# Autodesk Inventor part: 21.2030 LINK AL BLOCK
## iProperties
Created: 2007-01
Part Number: 21.2030 LINK AL BLOCK
Material: Aluminum-6061
Document SubType Name: Modeling
Designer: Andy Moles
Density: 2.71 g/cm^3
Author: Andy Moles
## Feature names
1. Base1
